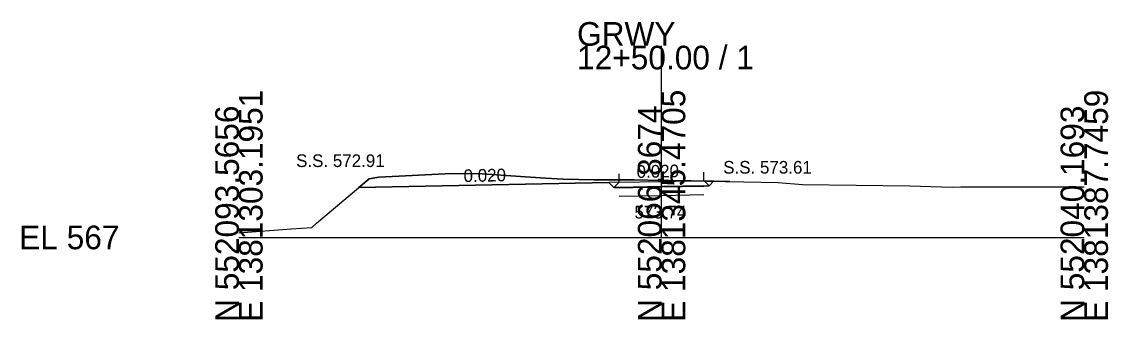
# Model space of a CAD drawing. Extents: x -26 to 103, y -10 to 3028.
# Drawn here: x -25.7 to 102.8, y 2490.3 to 2525.5 of the extents above; entities that cross this region are included whole.
import ezdxf

# ---------------------------------------------------------------- set-up
doc = ezdxf.new("R2010")
doc.units = 0
for name, color, linetype in [('Exist Cross Section Cell', 7, 'Continuous'), ('Exist XS Center Line Elevation Label', 7, 'Continuous'), ('Exist XS Ground Line', 7, 'Continuous'), ('Prop XS Dump Level', 7, 'Continuous'), ('Prop XS Earthwork Shape', 7, 'Continuous'), ('Prop XS EOT Tick Mark', 7, 'Continuous'), ('Prop XS Finish Grade', 7, 'Continuous'), ('Prop XS Finish Grade Earthwork', 7, 'Continuous'), ('Prop XS Finish Grade Pavement', 7, 'Continuous'), ('Prop XS Pvmt Edge Slope', 7, 'Continuous'), ('Prop XS SE Text', 7, 'Continuous'), ('Prop XS SS Elevation Text', 7, 'Continuous'), ('Prop XS Subgrade Earthwork', 7, 'Continuous')]:
    doc.layers.add(name, color=color, linetype=linetype)

msp = doc.modelspace()

# ---------------------------------------------------------------- linework, layer by layer
at = {"layer": 'Exist Cross Section Cell'}
for p, q in [((50, 2500), (50, 2522.69)), ((0, 2500), (50, 2500)), ((50, 2500), (100, 2500))]:
    msp.add_line(p, q, dxfattribs=at)
at = {"layer": 'Exist XS Ground Line'}
for p, q in [((9.16, 2501.69), (15.42, 2506.95)), ((15.42, 2506.95), (16.55, 2507.15)), ((16.55, 2507.15), (25.17, 2507.56)), ((25.17, 2507.56), (28.78, 2507.51)), ((28.78, 2507.51), (33.3, 2507.21)), ((33.3, 2507.21), (36.28, 2507)), ((36.28, 2507), (38.37, 2506.89)), ((38.37, 2506.89), (41.98, 2506.81)), ((41.98, 2506.81), (46.79, 2506.8)), ((46.79, 2506.8), (50, 2506.74)), ((50, 2506.74), (50.86, 2506.73)), ((50.86, 2506.73), (59.74, 2506.58)), ((59.74, 2506.58), (63.78, 2506.5)), ((63.78, 2506.5), (66.65, 2506.26)), ((66.65, 2506.26), (79.37, 2506.09)), ((79.37, 2506.09), (84.39, 2505.93)), ((84.39, 2505.93), (85.41, 2505.97)), ((85.41, 2505.97), (87.32, 2505.98)), ((87.32, 2505.98), (100, 2505.98)), ((8.63, 2501.18), (9.16, 2501.69)), ((0, 2500.55), (6.18, 2501)), ((6.18, 2501), (8.63, 2501.18))]:
    msp.add_line(p, q, dxfattribs=at)
at = {"layer": 'Prop XS Dump Level'}
for p, q in [((45, 2505.88), (50, 2505.98)), ((50, 2505.98), (55, 2506.08)), ((45, 2504.88), (50, 2504.98)), ((50, 2504.98), (55, 2505.08))]:
    msp.add_line(p, q, dxfattribs=at)
at = {"layer": 'Prop XS Earthwork Shape'}
for points in [[(55, 2506.1), (55.61, 2506.12), (56.13, 2506.64), (50.86, 2506.73), (50, 2506.74), (46.79, 2506.8), (41.98, 2506.81), (38.37, 2506.89), (36.28, 2507), (33.3, 2507.21), (28.78, 2507.51), (25.17, 2507.56), (16.55, 2507.15), (15.42, 2506.95), (14.19, 2505.91), (43.75, 2506.5), (44.36, 2505.89), (45, 2505.91), (50, 2506.01)], [(56.13, 2506.64), (56.18, 2506.68), (58.06, 2506.61)]]:
    msp.add_lwpolyline(points, close=True, dxfattribs=at)
at = {"layer": 'Prop XS EOT Tick Mark'}
for p, q in [((55, 2506.73), (55, 2507.73)), ((45, 2506.53), (45, 2507.53))]:
    msp.add_line(p, q, dxfattribs=at)
at = {"layer": 'Prop XS Finish Grade'}
for p, q in [((45, 2506.53), (43.75, 2506.5)), ((55, 2506.73), (56.18, 2506.68))]:
    msp.add_line(p, q, dxfattribs=at)
at = {"layer": 'Prop XS Finish Grade Earthwork'}
for p, q in [((43.75, 2506.5), (14.19, 2505.91)), ((56.18, 2506.68), (58.06, 2506.61))]:
    msp.add_line(p, q, dxfattribs=at)
at = {"layer": 'Prop XS Finish Grade Pavement'}
for p, q in [((45, 2506.53), (50, 2506.63)), ((50, 2506.63), (55, 2506.73))]:
    msp.add_line(p, q, dxfattribs=at)
at = {"layer": 'Prop XS Pvmt Edge Slope'}
for p, q in [((45, 2506.53), (44.36, 2505.89)), ((55, 2506.73), (55.61, 2506.12))]:
    msp.add_line(p, q, dxfattribs=at)
at = {"layer": 'Prop XS Subgrade Earthwork'}
for p, q in [((44.36, 2505.89), (43.75, 2506.5)), ((55.61, 2506.12), (56.18, 2506.68)), ((45, 2505.91), (44.36, 2505.89)), ((50, 2506.01), (45, 2505.91)), ((55, 2506.1), (50, 2506.01)), ((55, 2506.1), (55.61, 2506.12))]:
    msp.add_line(p, q, dxfattribs=at)

# ---------------------------------------------------------------- texts
at = {"layer": 'Exist Cross Section Cell'}
for s, p in [('GRWY', (40, 2522.69)), ('12+50.00 / 1', (40, 2519.89)), ('EL 567', (-26, 2498.6))]:
    msp.add_text(s, height=2.8, dxfattribs=at).set_placement(p)
for s, p in [('E 1381303.1951', (2.8, 2490)), ('E 1381345.4705', (52.8, 2490)), ('E 1381387.7459', (102.8, 2490)), ('N 552093.5656', (0, 2490)), ('N 552066.8674', (50, 2490)), ('N 552040.1693', (100, 2490))]:
    msp.add_text(s, height=2.8, rotation=90, dxfattribs=at).set_placement(p)
at = {"layer": 'Exist XS Center Line Elevation Label'}
msp.add_text('573.74', height=1.5, dxfattribs=at).set_placement((46.79, 2502.24))
at = {"layer": 'Prop XS Dump Level'}
for p in [(43, 2505.68), (57, 2505.96)]:
    msp.add_text('Case1', height=0.04, dxfattribs=at).set_placement(p)
at = {"layer": 'Prop XS SE Text'}
for p in [(26.59, 2506.55), (47.06, 2507.03)]:
    msp.add_text('0.020', height=1.5, rotation=1.1458, dxfattribs=at).set_placement(p)
at = {"layer": 'Prop XS SS Elevation Text'}
for s, p in [('S.S. 572.91', (6.76, 2508.33)), ('S.S. 573.61', (57.29, 2507.55))]:
    msp.add_text(s, height=1.5, dxfattribs=at).set_placement(p)

doc.saveas('drawing.dxf')
